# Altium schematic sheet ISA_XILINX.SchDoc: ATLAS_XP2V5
size 558 x 431 mm; Organization: IMP Automatika d.o.o.; Revision: V5
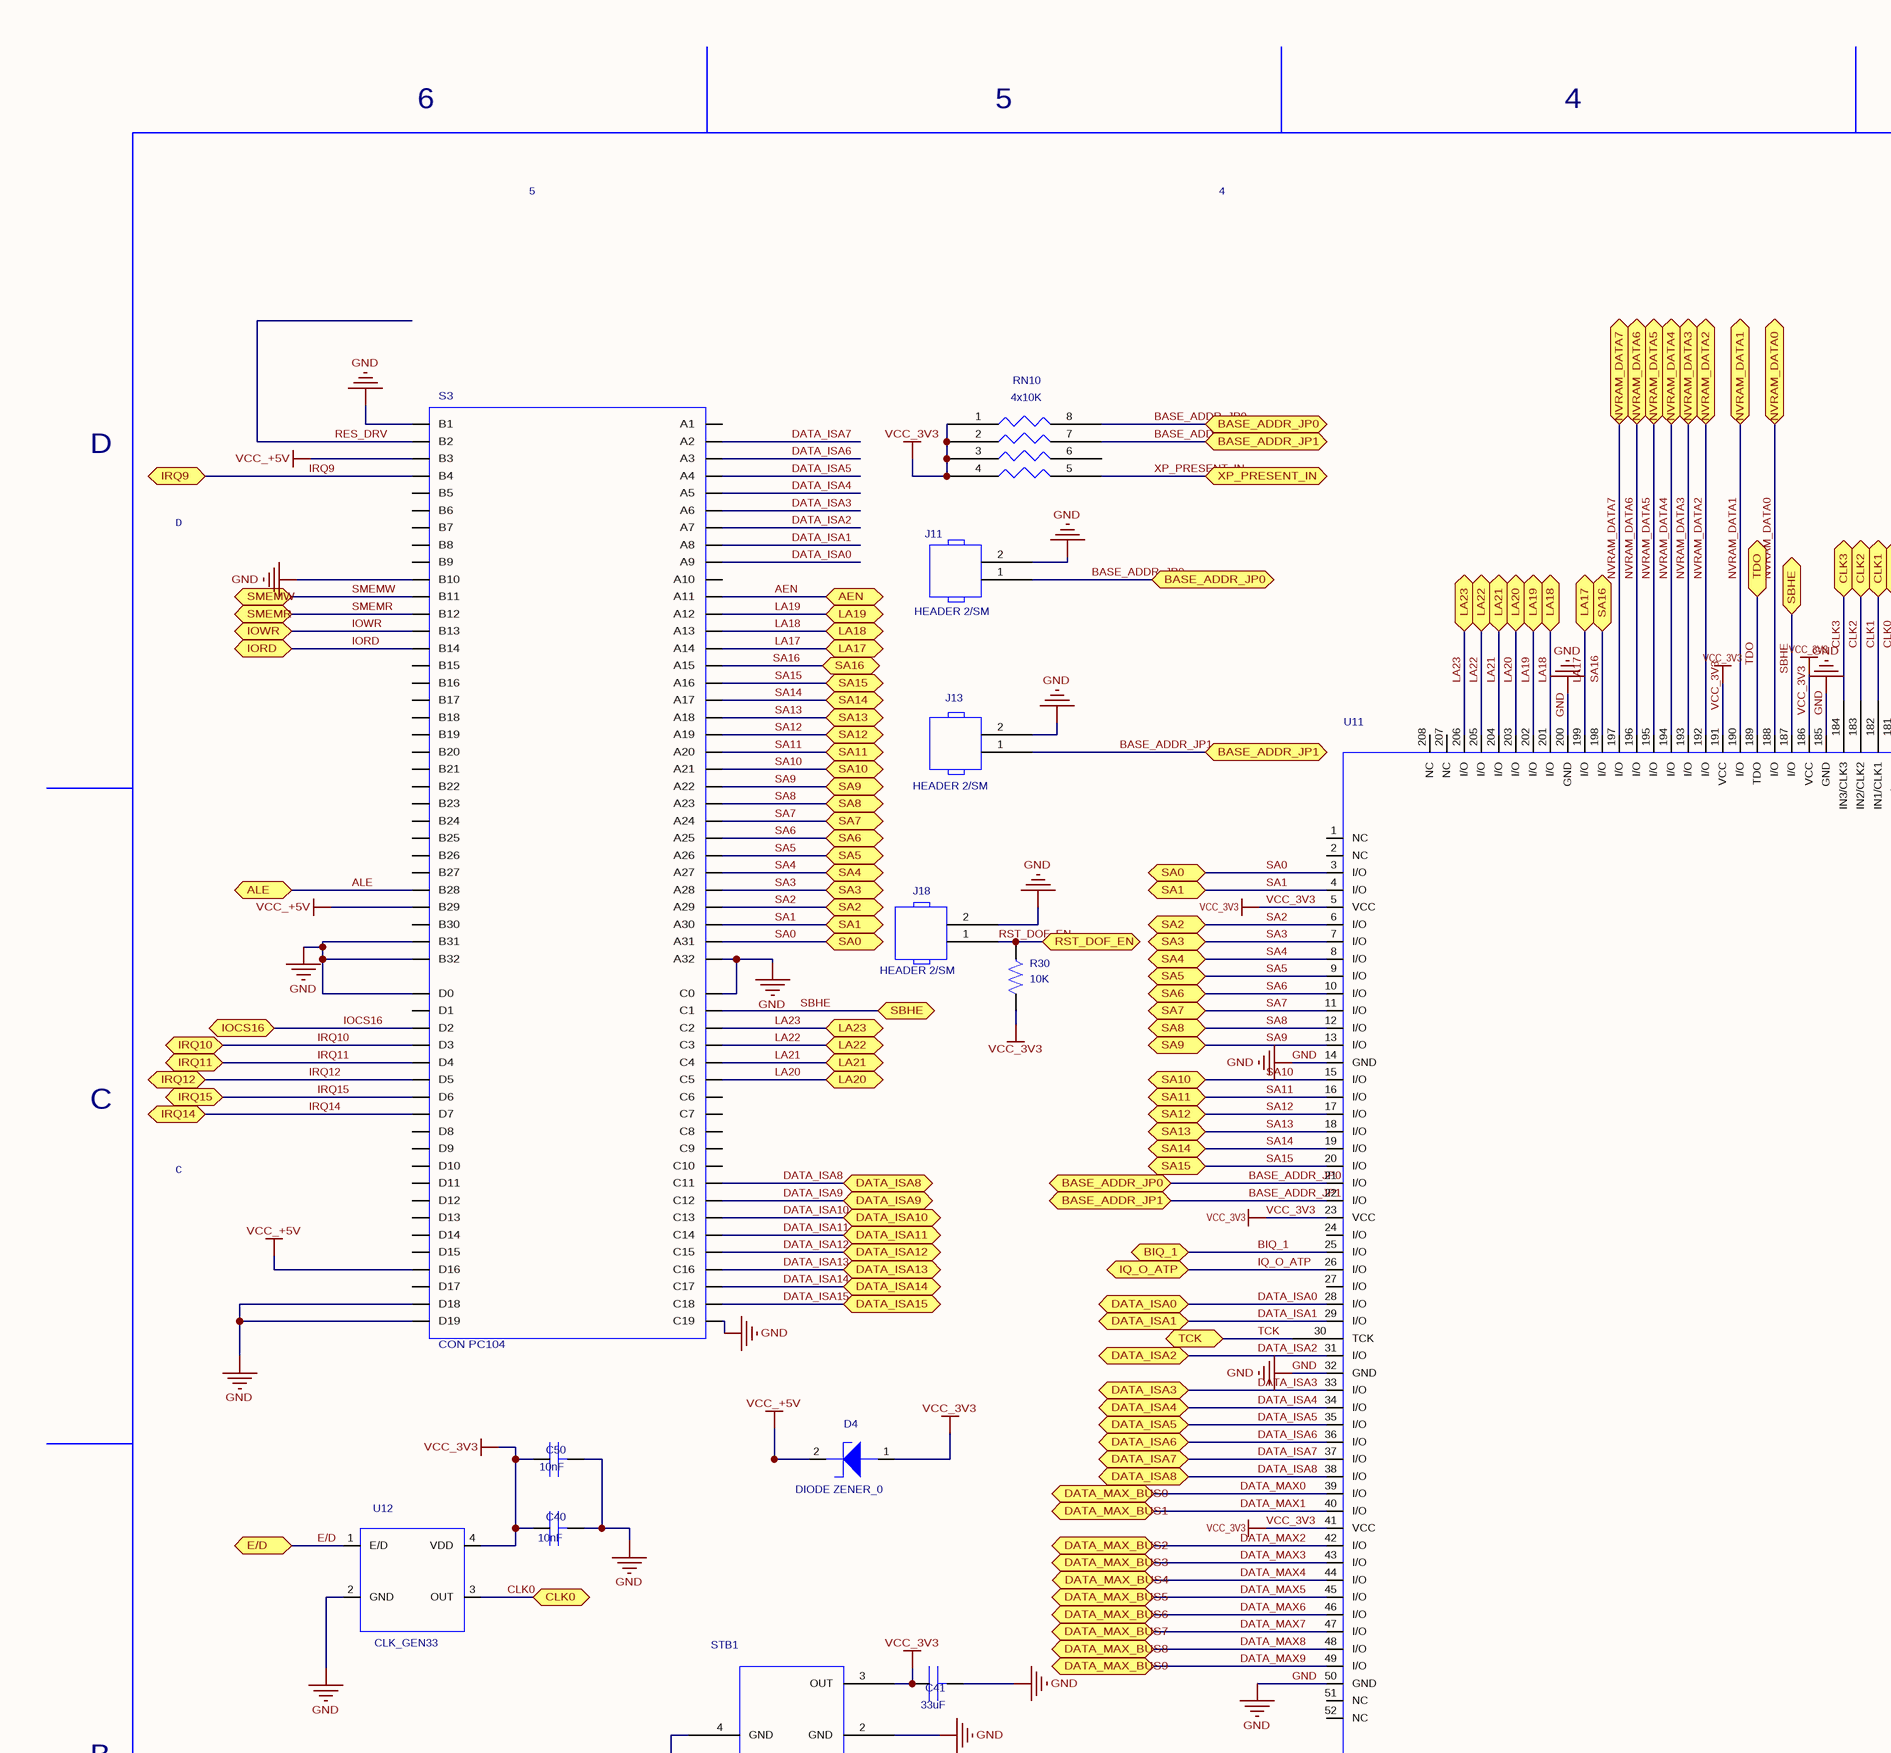
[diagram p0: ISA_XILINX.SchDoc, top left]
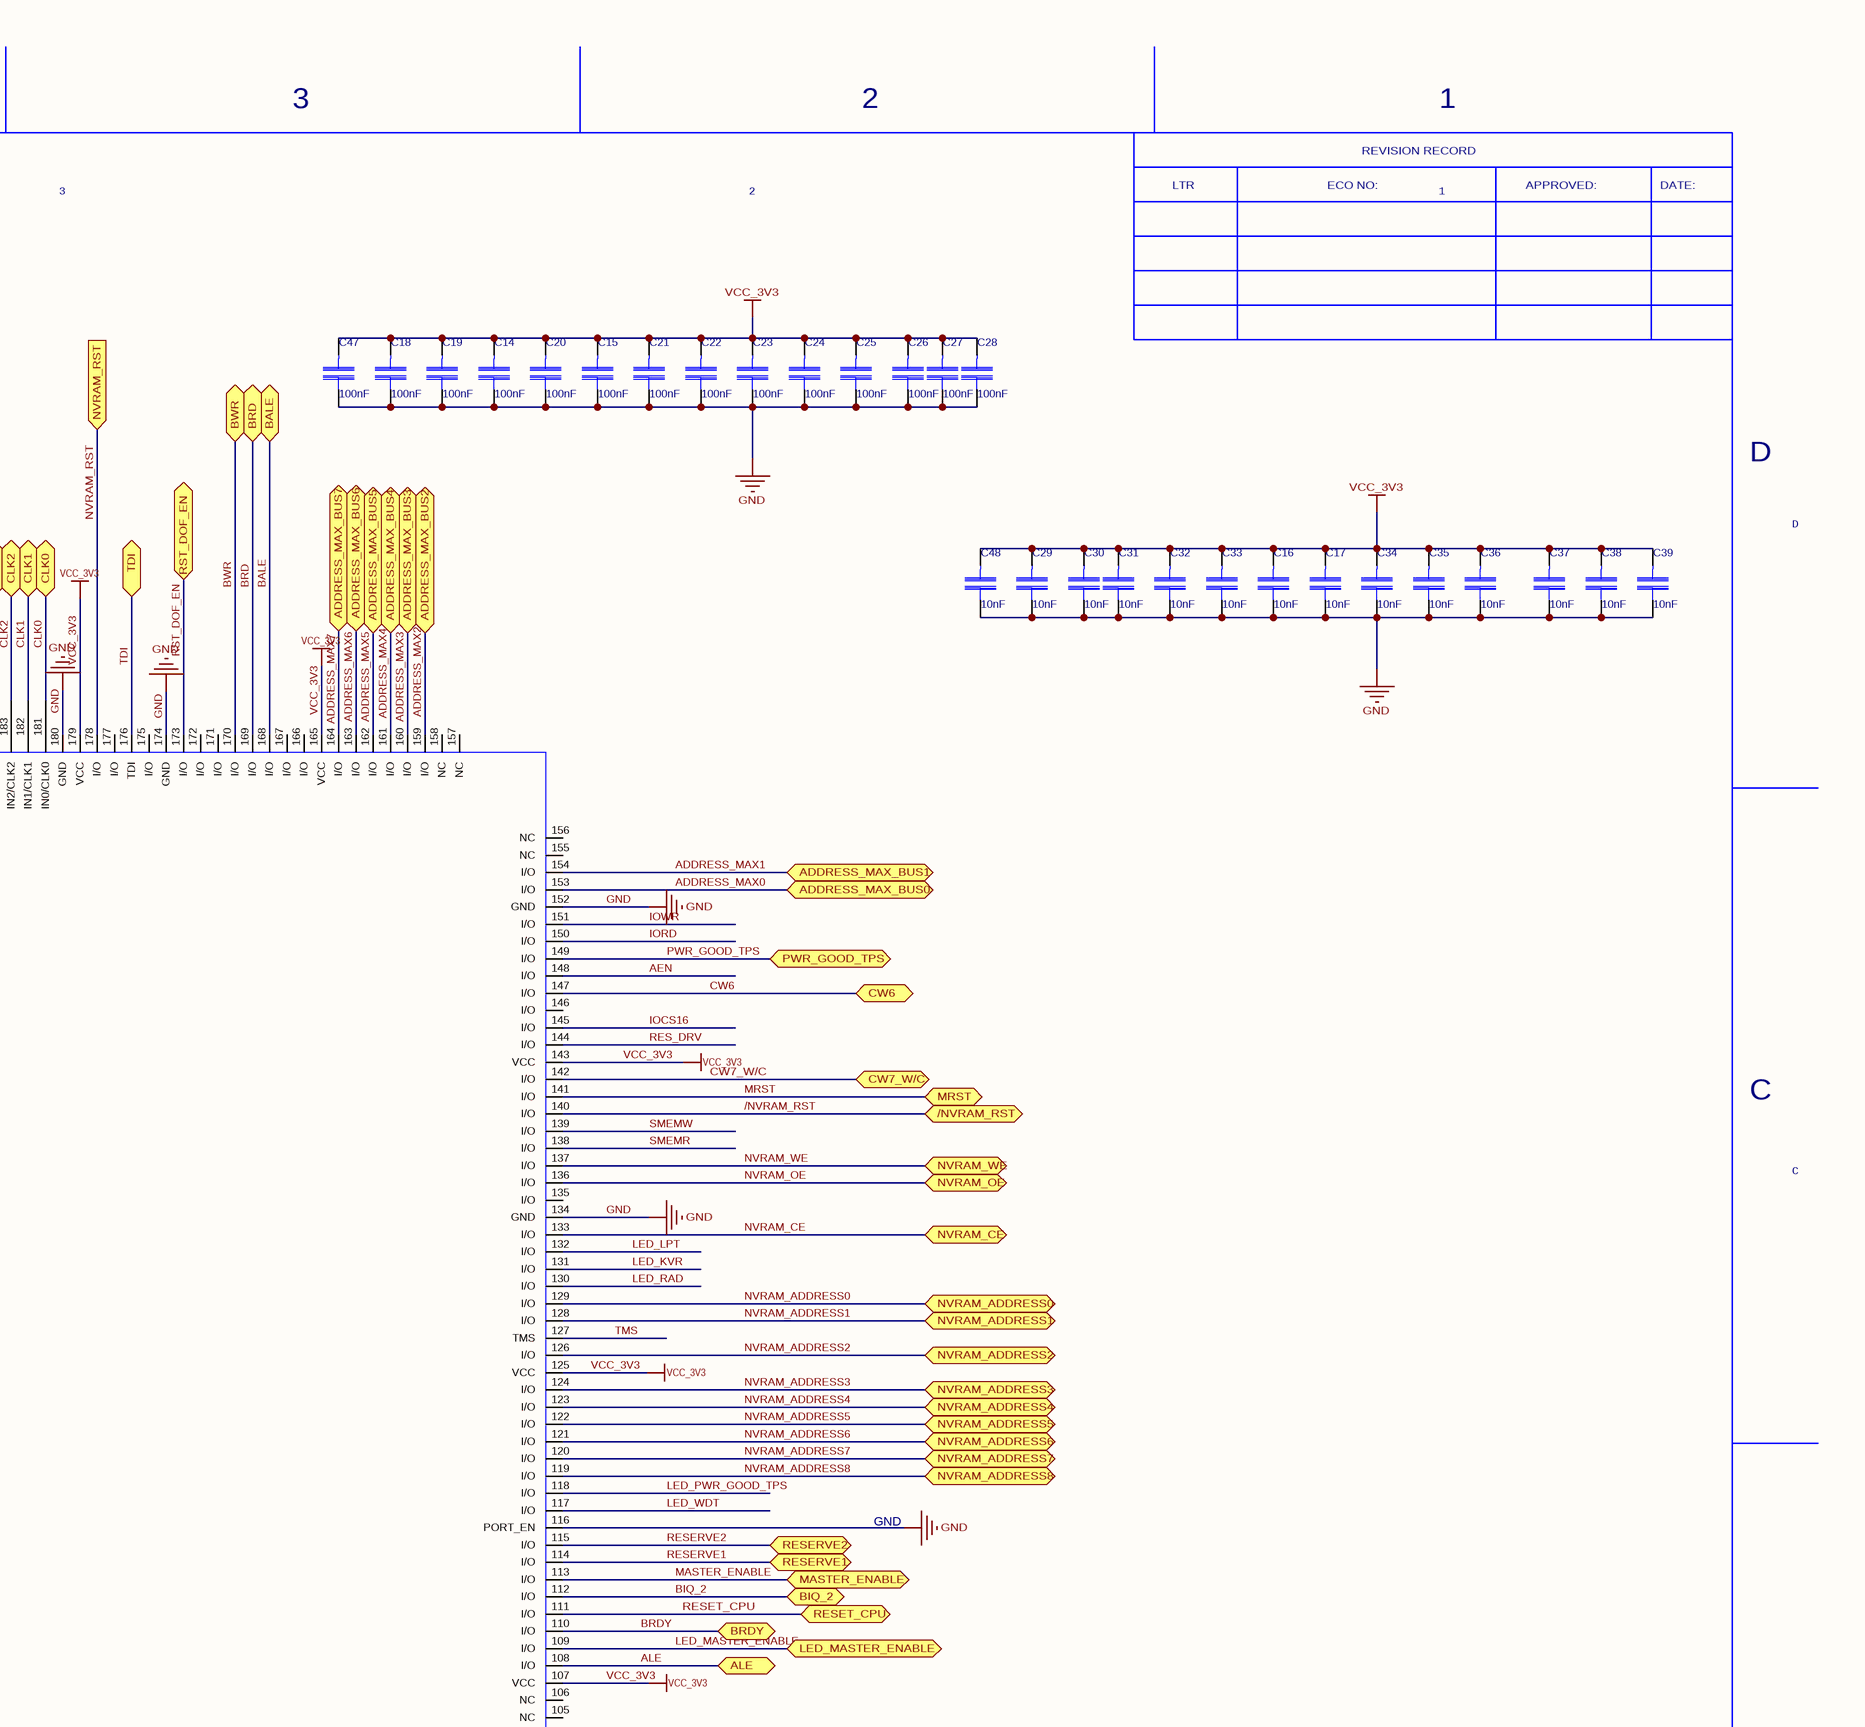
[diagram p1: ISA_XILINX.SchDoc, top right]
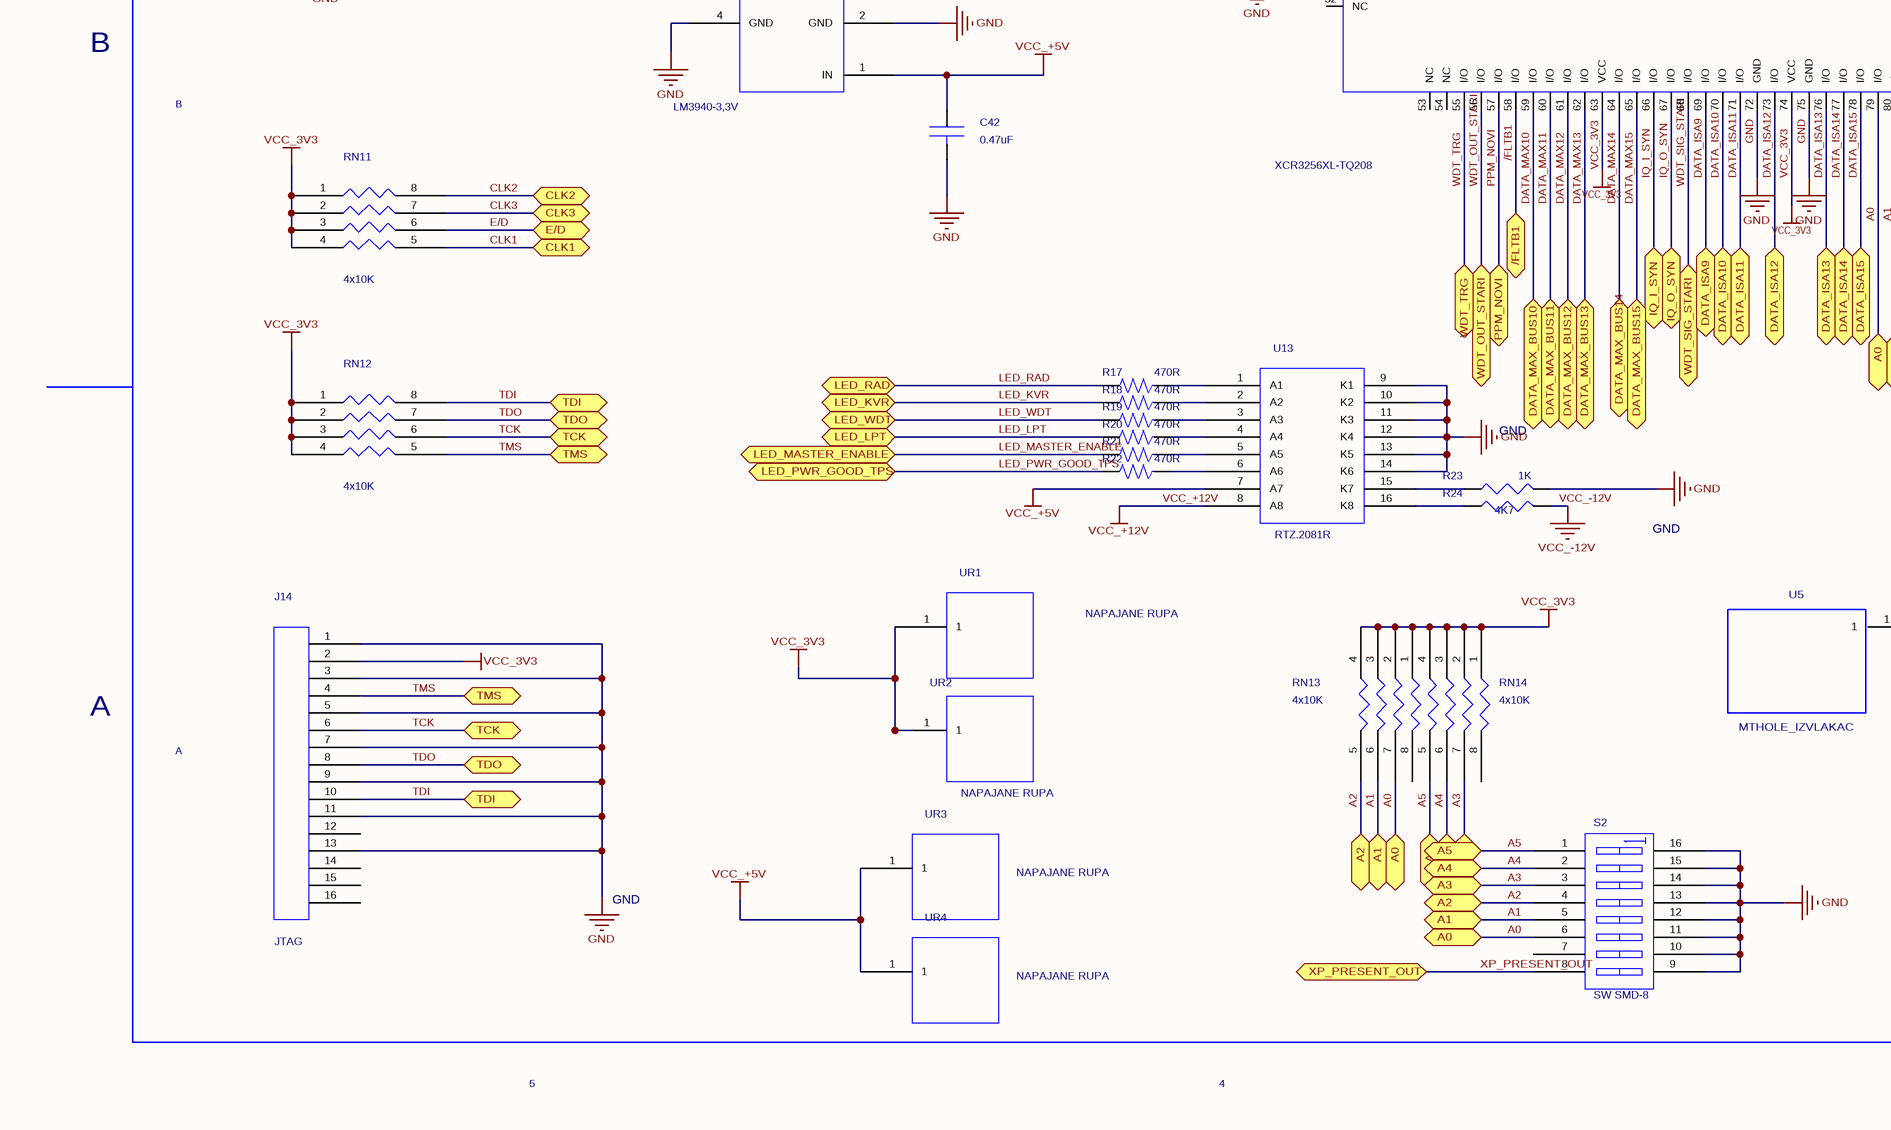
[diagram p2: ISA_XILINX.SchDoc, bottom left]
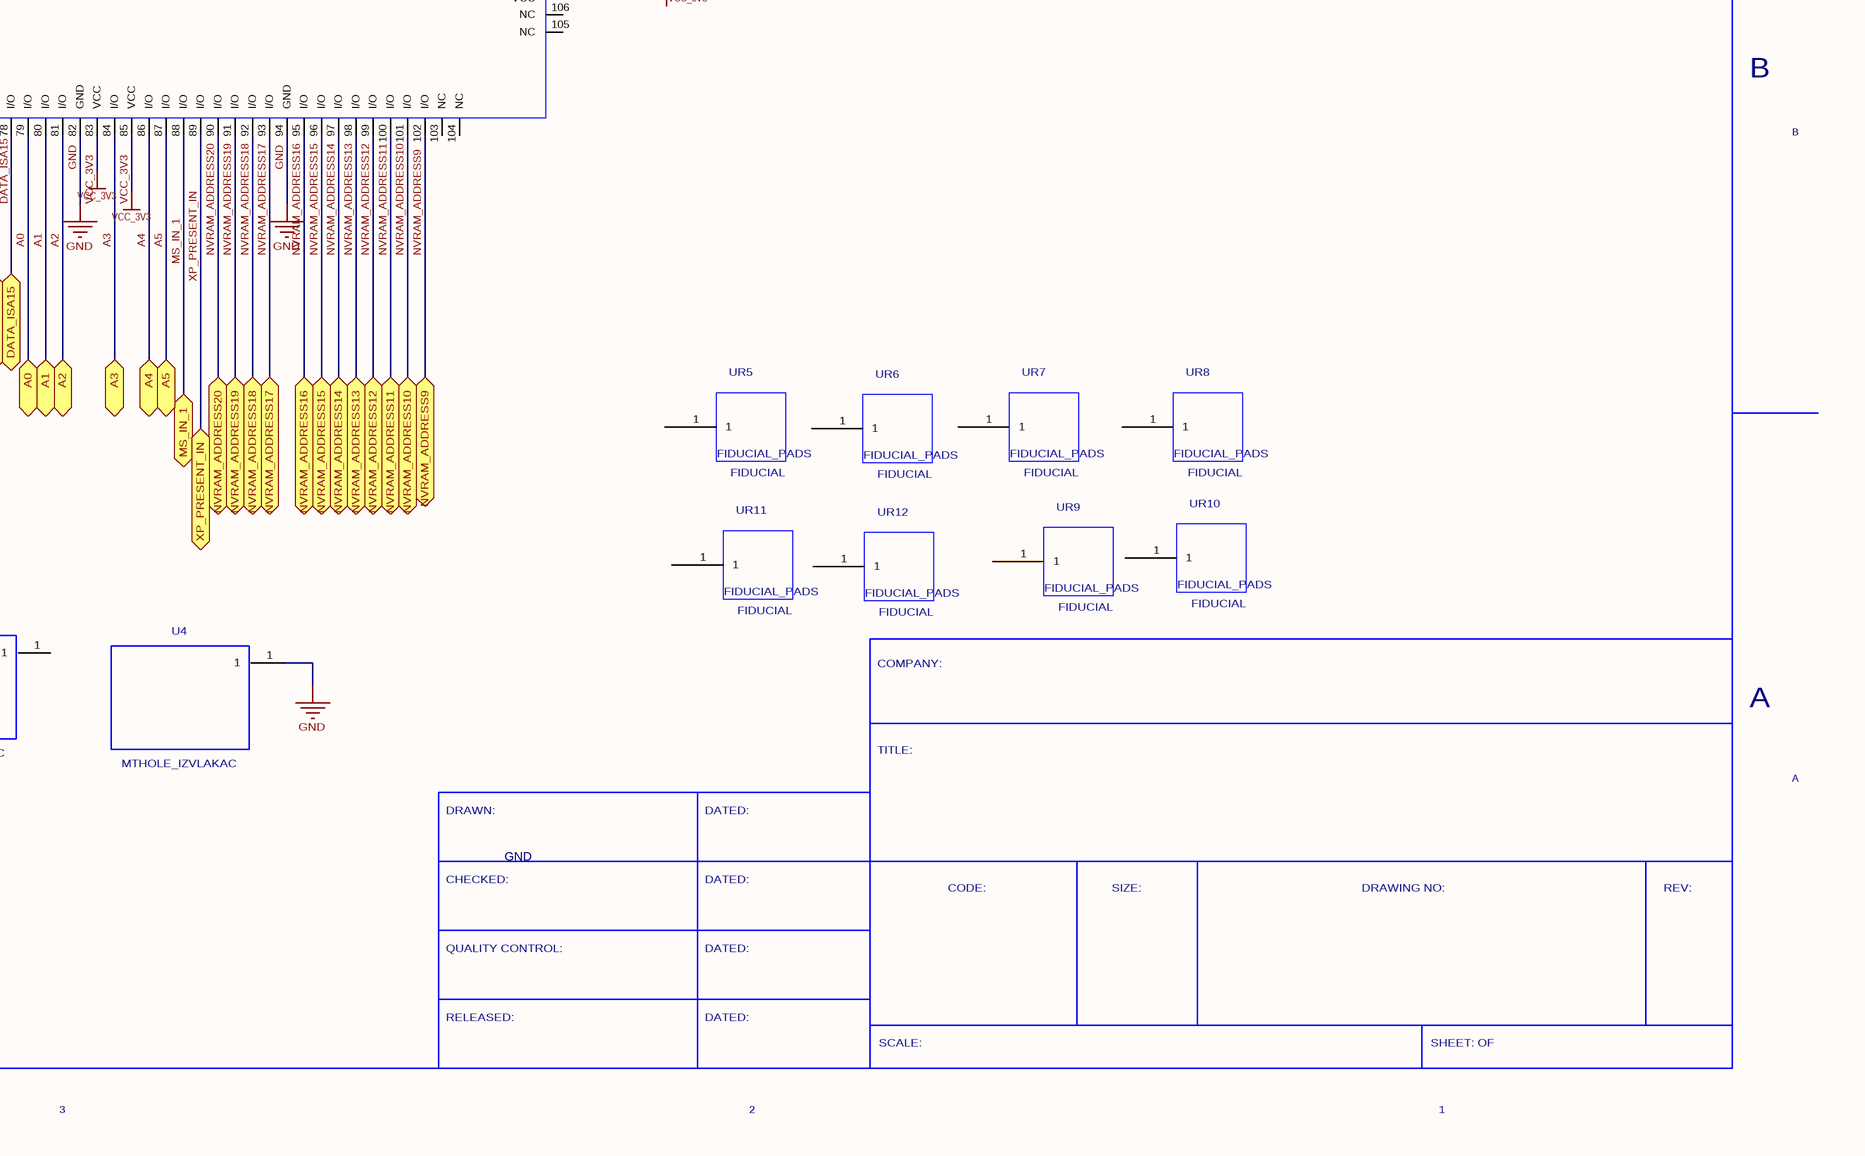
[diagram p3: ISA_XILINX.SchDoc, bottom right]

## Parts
C14  value 100nF  [SM/C_0805]  (hidden comment: C)
C15  value 100nF  [SM/C_0805]  (hidden comment: C)
C16  value 10nF  [SM/C_0805]  (hidden comment: C)
C17  value 10nF  [SM/C_0805]  (hidden comment: C)
C18  value 100nF  [SM/C_0805]  (hidden comment: C)
C19  value 100nF  [SM/C_0805]  (hidden comment: C)
C20  value 100nF  [SM/C_0805]  (hidden comment: C)
C21  value 100nF  [SM/C_0805]  (hidden comment: C)
C22  value 100nF  [SM/C_0805]  (hidden comment: C)
C23  value 100nF  [SM/C_0805]  (hidden comment: C)
C24  value 100nF  [SM/C_0805]  (hidden comment: C)
C25  value 100nF  [SM/C_0805]  (hidden comment: C)
C26  value 100nF  [SM/C_0805]  (hidden comment: C)
C27  value 100nF  [SM/C_0805]  (hidden comment: C)
C28  value 100nF  [SM/C_0805]  (hidden comment: C)
C29  value 10nF  [SM/C_0805]  (hidden comment: C)
C30  value 10nF  [SM/C_0805]  (hidden comment: C)
C31  value 10nF  [SM/C_0805]  (hidden comment: C)
C32  value 10nF  [SM/C_0805]  (hidden comment: C)
C33  value 10nF  [SM/C_0805]  (hidden comment: C)
C34  value 10nF  [SM/C_0805]  (hidden comment: C)
C35  value 10nF  [SM/C_0805]  (hidden comment: C)
C36  value 10nF  [SM/C_0805]  (hidden comment: C)
C37  value 10nF  [SM/C_0805]  (hidden comment: C)
C38  value 10nF  [SM/C_0805]  (hidden comment: C)
C39  value 10nF  [SM/C_0805]  (hidden comment: C)
C40  value 10nF  [SM/C_0805]  (hidden comment: C_4)
C41  value 33uF  [CASE_D_MILOS]  (hidden comment: C_4)
C42  value 0.47uF  [CASE_B_MILOS]  (hidden comment: C_4)
C47  value 100nF  [SM/C_0805]  (hidden comment: C)
C48  value 10nF  [SM/C_0805]  (hidden comment: C)
C50  value 10nF  [SM/C_0805]  (hidden comment: C_4)
D4  value DIODE ZENER_0  [BZV55-C3V3]  (hidden comment: DIODE_ZENER_1)
J11  value HEADER 2/SM  [JUMPER_100]  (hidden comment: HEADER_2/SM)
J13  value HEADER 2/SM  [JUMPER_100]  (hidden comment: HEADER_2/SM)
J14  value JTAG  [JTAG_SMD_REV2]  (hidden comment: CONN_FLEX_16/SM)
J18  value HEADER 2/SM  [JUMPER_100]  (hidden comment: HEADER_2/SM)
R17  value 470R  [SM/R_1206]  (hidden comment: R)
R18  value 470R  [SM/R_1206]  (hidden comment: R)
R19  value 470R  [SM/R_1206]  (hidden comment: R)
R20  value 470R  [SM/R_1206]  (hidden comment: R)
R21  value 470R  [SM/R_1206]  (hidden comment: R)
R22  value 470R  [SM/R_1206]  (hidden comment: R)
R23  value 1K  [SM/R_1206]  (hidden comment: RESISTOR_2)
R24  value 4K7  [SM/R_1206]  (hidden comment: RESISTOR_2)
R30  value 10K  [SM/R_1206]  (hidden comment: R)
RN10  value 4x10K  [SMD_RX4]  (hidden comment: RESAR_IS_4/SM)
RN11  value 4x10K  [SMD_RX4]  (hidden comment: RESAR_IS_4/SM)
RN12  value 4x10K  [SMD_RX4]  (hidden comment: RESAR_IS_4/SM)
RN13  value 4x10K  [SMD_RX4]  (hidden comment: RESAR_IS_4/SM)
RN14  value 4x10K  [SMD_RX4]  (hidden comment: RESAR_IS_4/SM)
S2  value SW SMD-8  [SMD_DIPSW_100]  (hidden comment: SW_DIP-8)
S3  value CON PC104  [PC104_REV13]  (hidden comment: CON_EISAE_0)
STB1  value LM3940-3,3V  [TO263AA_GND_PLANE_REV1]  (hidden comment: LM3940-3_3V)
U4  MTHOLE_IZVLAKAC  [MTH_IZVLAKAC_PADS]
U5  MTHOLE_IZVLAKAC  [MTH_IZVLAKAC_PADS]
U11  XCR3256XL-TQ208  [QUAD.50M/208/WG30.60]
U12  CLK_GEN33  [CLK_GEN33_REV1]
U13  value RTZ.2081R  [LED_8_REV3_PADS]  (hidden comment: LED8X1)
UR1  value NAPAJANE RUPA  [NAPAJANJE_RUPA_REV1]  (hidden comment: NAPAJANE_RUPA)
UR2  value NAPAJANE RUPA  [NAPAJANJE_RUPA_REV1]  (hidden comment: NAPAJANE_RUPA)
UR3  value NAPAJANE RUPA  [NAPAJANJE_RUPA_REV1]  (hidden comment: NAPAJANE_RUPA)
UR4  value NAPAJANE RUPA  [NAPAJANJE_RUPA_REV1]  (hidden comment: NAPAJANE_RUPA)
UR5  FIDUCIAL_PADS  value FIDUCIAL  [FIDUCIAL_R_TOP]
UR6  FIDUCIAL_PADS  value FIDUCIAL  [FIDUCIAL_R_TOP]
UR7  FIDUCIAL_PADS  value FIDUCIAL  [FIDUCIAL_R_TOP]
UR8  FIDUCIAL_PADS  value FIDUCIAL  [FIDUCIAL_R_TOP]
UR9  FIDUCIAL_PADS  value FIDUCIAL  [FIDUCIAL_R_TOP]
UR10  FIDUCIAL_PADS  value FIDUCIAL  [FIDUCIAL_R_TOP]
UR11  FIDUCIAL_PADS  value FIDUCIAL  [FIDUCIAL_R_TOP]
UR12  FIDUCIAL_PADS  value FIDUCIAL  [FIDUCIAL_R_TOP]

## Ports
/FLTB1 (bidir), /NVRAM_RST (bidir), A0 (bidir), A1 (bidir), A2 (bidir), A3 (bidir), A4 (bidir), A5 (bidir), ADDRESS_MAX_BUS0 (bidir), ADDRESS_MAX_BUS1 (bidir), ADDRESS_MAX_BUS2 (bidir), ADDRESS_MAX_BUS3 (bidir), ADDRESS_MAX_BUS4 (bidir), ADDRESS_MAX_BUS5 (bidir), ADDRESS_MAX_BUS6 (bidir), ADDRESS_MAX_BUS7 (bidir), AEN (bidir), ALE (bidir), BALE (bidir), BASE_ADDR_JP0 (bidir), BASE_ADDR_JP1 (bidir), BIQ_1 (bidir), BIQ_2 (bidir), BRD (bidir), BRDY (bidir), BWR (bidir), CLK0 (bidir), CLK1 (bidir), CLK2 (bidir), CLK3 (bidir), CW6 (bidir), CW7_W/C (bidir), DATA_ISA0 (bidir), DATA_ISA1 (bidir), DATA_ISA2 (bidir), DATA_ISA3 (bidir), DATA_ISA4 (bidir), DATA_ISA5 (bidir), DATA_ISA6 (bidir), DATA_ISA7 (bidir), DATA_ISA8 (bidir), DATA_ISA9 (bidir), DATA_ISA10 (bidir), DATA_ISA11 (bidir), DATA_ISA12 (bidir), DATA_ISA13 (bidir), DATA_ISA14 (bidir), DATA_ISA15 (bidir), DATA_MAX_BUS0 (bidir), DATA_MAX_BUS1 (bidir), DATA_MAX_BUS2 (bidir), DATA_MAX_BUS3 (bidir), DATA_MAX_BUS4 (bidir), DATA_MAX_BUS5 (bidir), DATA_MAX_BUS6 (bidir), DATA_MAX_BUS7 (bidir), DATA_MAX_BUS8 (bidir), DATA_MAX_BUS9 (bidir), DATA_MAX_BUS10 (bidir), DATA_MAX_BUS11 (bidir), DATA_MAX_BUS12 (bidir), DATA_MAX_BUS13 (bidir), DATA_MAX_BUS14 (bidir), DATA_MAX_BUS15 (bidir), E/D (bidir), IOCS16 (bidir), IORD (bidir), IOWR (bidir), IQ_I_SYN (bidir), IQ_O_ATP (bidir), IQ_O_SYN (bidir), IRQ9 (bidir), IRQ10 (bidir), IRQ11 (bidir), IRQ12 (bidir), IRQ14 (bidir), IRQ15 (bidir), LA17 (bidir), LA18 (bidir), LA19 (bidir), LA20 (bidir), LA21 (bidir), LA22 (bidir), LA23 (bidir), LED_KVR (bidir), LED_LPT (bidir), LED_MASTER_ENABLE (bidir), LED_PWR_GOOD_TPS (bidir), LED_RAD (bidir), LED_WDT (bidir), MASTER_ENABLE (bidir), MRST (bidir), MS_IN_1 (bidir), NVRAM_ADDRESS0 (bidir), NVRAM_ADDRESS1 (bidir), NVRAM_ADDRESS2 (bidir), NVRAM_ADDRESS3 (bidir), NVRAM_ADDRESS4 (bidir), NVRAM_ADDRESS5 (bidir), NVRAM_ADDRESS6 (bidir), NVRAM_ADDRESS7 (bidir), NVRAM_ADDRESS8 (bidir), NVRAM_ADDRESS9 (bidir), NVRAM_ADDRESS10 (bidir), NVRAM_ADDRESS11 (bidir), NVRAM_ADDRESS12 (bidir), NVRAM_ADDRESS13 (bidir), NVRAM_ADDRESS14 (bidir), NVRAM_ADDRESS15 (bidir), NVRAM_ADDRESS16 (bidir), NVRAM_ADDRESS17 (bidir), NVRAM_ADDRESS18 (bidir), NVRAM_ADDRESS19 (bidir), NVRAM_ADDRESS20 (bidir), NVRAM_CE (bidir), NVRAM_DATA0 (bidir), NVRAM_DATA1 (bidir), NVRAM_DATA2 (bidir), NVRAM_DATA3 (bidir), NVRAM_DATA4 (bidir), NVRAM_DATA5 (bidir), NVRAM_DATA6 (bidir), NVRAM_DATA7 (bidir), NVRAM_OE (bidir), NVRAM_RST, NVRAM_WE (bidir), PPM_NOVI (bidir), PWR_GOOD_TPS (bidir), RESERVE1 (bidir), RESERVE2 (bidir), RESET_CPU (bidir), RST_DOF_EN (bidir), SA0 (bidir), SA1 (bidir), SA2 (bidir), SA3 (bidir), SA4 (bidir), SA5 (bidir), SA6 (bidir), SA7 (bidir), SA8 (bidir), SA9 (bidir), SA10 (bidir), SA11 (bidir), SA12 (bidir), SA13 (bidir), SA14 (bidir), SA15 (bidir), SA16 (bidir), SBHE (bidir), SMEMR (bidir), SMEMW (bidir), TCK (bidir), TDI (bidir), TDO (bidir), TMS (bidir), WDT_OUT_STARI (bidir), WDT_SIG_STARI (bidir), WDT_TRG (bidir), XP_PRESENT_IN (bidir), XP_PRESENT_OUT (bidir)

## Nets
GND: C14.2 C15.2 C16.2 C17.2 C18.2 C19.2 C20.2 C21.2 C22.2 C23.2 C24.2 C25.2 C26.2 C27.2 C28.2 C29.2 C30.2 C31.2 C32.2 C33.2 C34.2 C35.2 C36.2 C37.2 C38.2 C39.2 C40.2 C41.2 C42.2 C47.2 C48.2 C50.2 J11.2 J13.2 J14.1 J14.3 J14.5 J14.7 J14.9 J14.11 J14.13 J18.2 R23.2 S2.9(B8) S2.10(B7) S2.11(B6) S2.12(B5) S2.13(B4) S2.14(B3) S2.15(B2) S2.16(B1) S3.A32 S3.B1 S3.B10 S3.B31 S3.B32 S3.C0 S3.C19 S3.D0 S3.D18 S3.D19 STB1.2(GND) STB1.4(GND) U4.1 U11.14(GND) U11.32(GND) U11.50(GND) U11.72(GND) U11.75(GND) U11.82(GND) U11.94(GND) U11.116(PORT_EN) U11.134(GND) U11.152(GND) U11.174(GND) U11.180(GND) U11.185(GND) U11.200(GND) U12.2(GND) U13.9(K1) U13.10(K2) U13.11(K3) U13.12(K4) U13.13(K5) U13.14(K6)
VCC_3V3: C14.1 C15.1 C16.1 C17.1 C18.1 C19.1 C20.1 C21.1 C22.1 C23.1 C24.1 C25.1 C26.1 C27.1 C28.1 C29.1 C30.1 C31.1 C32.1 C33.1 C34.1 C35.1 C36.1 C37.1 C38.1 C39.1 C40.1 C41.1 C47.1 C48.1 C50.1 D4.1(ANODE) J14.2 R30.2 RN10.1 RN10.2 RN10.3 RN10.4 RN11.1 RN11.2 RN11.3 RN11.4 RN12.1 RN12.2 RN12.3 RN12.4 RN13.1 RN13.2 RN13.3 RN13.4 RN14.1 RN14.2 RN14.3 RN14.4 STB1.3(OUT) U11.5(VCC) U11.23(VCC) U11.41(VCC) U11.63(VCC) U11.74(VCC) U11.83(VCC) U11.85(VCC) U11.107(VCC) U11.125(VCC) U11.143(VCC) U11.165(VCC) U11.179(VCC) U11.186(VCC) U11.191(VCC) U12.4(VDD) UR1.1 UR2.1
VCC_+5V: C42.1 D4.2(CATHODE) S3.B3 S3.B29 S3.D16 STB1.1(IN) U13.7(A7) UR3.1 UR4.1
VCC_+12V: U13.8(A8)
VCC_-12V: R24.2
/FLTB1: U11.58(I/O) ; port /FLTB1
/NVRAM_RST: U11.140(I/O) ; port /NVRAM_RST
A0: RN13.7 S2.6(A6) U11.79(I/O) ; port A0
A1: RN13.6 S2.5(A5) U11.80(I/O) ; port A1
A2: RN13.5 S2.4(A4) U11.81(I/O) ; port A2
A3: RN14.7 S2.3(A3) U11.84(I/O) ; port A3
A4: RN14.6 S2.2(A2) U11.86(I/O) ; port A4
A5: RN14.5 S2.1(A1) U11.87(I/O) ; port A5
ADDRESS_MAX0: U11.153(I/O) ; port ADDRESS_MAX_BUS0
ADDRESS_MAX1: U11.154(I/O) ; port ADDRESS_MAX_BUS1
ADDRESS_MAX2: U11.159(I/O) ; port ADDRESS_MAX_BUS2
ADDRESS_MAX3: U11.160(I/O) ; port ADDRESS_MAX_BUS3
ADDRESS_MAX4: U11.161(I/O) ; port ADDRESS_MAX_BUS4
ADDRESS_MAX5: U11.162(I/O) ; port ADDRESS_MAX_BUS5
ADDRESS_MAX6: U11.163(I/O) ; port ADDRESS_MAX_BUS6
ADDRESS_MAX7: U11.164(I/O) ; port ADDRESS_MAX_BUS7
AEN: S3.A11 U11.148(I/O) ; port AEN
ALE: S3.B28 U11.108(I/O) ; port ALE
BALE: U11.168(I/O) ; port BALE
BASE_ADDR_JP0: J11.1 RN10.8 U11.21(I/O) ; port BASE_ADDR_JP0
BASE_ADDR_JP1: J13.1 RN10.7 U11.22(I/O) ; port BASE_ADDR_JP1
BIQ_1: U11.25(I/O) ; port BIQ_1
BIQ_2: U11.112(I/O) ; port BIQ_2
BRD: U11.169(I/O) ; port BRD
BRDY: U11.110(I/O) ; port BRDY
BWR: U11.170(I/O) ; port BWR
CLK0: U11.181(IN0/CLK0) U12.3(OUT) ; port CLK0
CLK1: RN11.5 U11.182(IN1/CLK1) ; port CLK1
CLK2: RN11.8 U11.183(IN2/CLK2) ; port CLK2
CLK3: RN11.7 U11.184(IN3/CLK3) ; port CLK3
CW6: U11.147(I/O) ; port CW6
CW7_W/C: U11.142(I/O) ; port CW7_W/C
DATA_ISA0: S3.A9 U11.28(I/O) ; port DATA_ISA0
DATA_ISA1: S3.A8 U11.29(I/O) ; port DATA_ISA1
DATA_ISA2: S3.A7 U11.31(I/O) ; port DATA_ISA2
DATA_ISA3: S3.A6 U11.33(I/O) ; port DATA_ISA3
DATA_ISA4: S3.A5 U11.34(I/O) ; port DATA_ISA4
DATA_ISA5: S3.A4 U11.35(I/O) ; port DATA_ISA5
DATA_ISA6: S3.A3 U11.36(I/O) ; port DATA_ISA6
DATA_ISA7: S3.A2 U11.37(I/O) ; port DATA_ISA7
DATA_ISA8: S3.C11 U11.38(I/O) ; port DATA_ISA8
DATA_ISA9: S3.C12 U11.69(I/O) ; port DATA_ISA9
DATA_ISA10: S3.C13 U11.70(I/O) ; port DATA_ISA10
DATA_ISA11: S3.C14 U11.71(I/O) ; port DATA_ISA11
DATA_ISA12: S3.C15 U11.73(I/O) ; port DATA_ISA12
DATA_ISA13: S3.C16 U11.76(I/O) ; port DATA_ISA13
DATA_ISA14: S3.C17 U11.77(I/O) ; port DATA_ISA14
DATA_ISA15: S3.C18 U11.78(I/O) ; port DATA_ISA15
DATA_MAX0: U11.39(I/O) ; port DATA_MAX_BUS0
DATA_MAX1: U11.40(I/O) ; port DATA_MAX_BUS1
DATA_MAX2: U11.42(I/O) ; port DATA_MAX_BUS2
DATA_MAX3: U11.43(I/O) ; port DATA_MAX_BUS3
DATA_MAX4: U11.44(I/O) ; port DATA_MAX_BUS4
DATA_MAX5: U11.45(I/O) ; port DATA_MAX_BUS5
DATA_MAX6: U11.46(I/O) ; port DATA_MAX_BUS6
DATA_MAX7: U11.47(I/O) ; port DATA_MAX_BUS7
DATA_MAX8: U11.48(I/O) ; port DATA_MAX_BUS8
DATA_MAX9: U11.49(I/O) ; port DATA_MAX_BUS9
DATA_MAX10: U11.59(I/O) ; port DATA_MAX_BUS10
DATA_MAX11: U11.60(I/O) ; port DATA_MAX_BUS11
DATA_MAX12: U11.61(I/O) ; port DATA_MAX_BUS12
DATA_MAX13: U11.62(I/O) ; port DATA_MAX_BUS13
DATA_MAX14: U11.64(I/O) ; port DATA_MAX_BUS14
DATA_MAX15: U11.65(I/O) ; port DATA_MAX_BUS15
E/D: RN11.6 U12.1(E/D) ; port E/D
IOCS16: S3.D2 U11.145(I/O) ; port IOCS16
IORD: S3.B14 U11.150(I/O) ; port IORD
IOWR: S3.B13 U11.151(I/O) ; port IOWR
IQ_I_SYN: U11.66(I/O) ; port IQ_I_SYN
IQ_O_ATP: U11.26(I/O) ; port IQ_O_ATP
IQ_O_SYN: U11.67(I/O) ; port IQ_O_SYN
IRQ9: S3.B4 ; port IRQ9
IRQ10: S3.D3 ; port IRQ10
IRQ11: S3.D4 ; port IRQ11
IRQ12: S3.D5 ; port IRQ12
IRQ14: S3.D7 ; port IRQ14
IRQ15: S3.D6 ; port IRQ15
LA17: S3.A14 U11.199(I/O) ; port LA17
LA18: S3.A13 U11.201(I/O) ; port LA18
LA19: S3.A12 U11.202(I/O) ; port LA19
LA20: S3.C5 U11.203(I/O) ; port LA20
LA21: S3.C4 U11.204(I/O) ; port LA21
LA22: S3.C3 U11.205(I/O) ; port LA22
LA23: S3.C2 U11.206(I/O) ; port LA23
LED_KVR: R18.2 U11.131(I/O) ; port LED_KVR
LED_LPT: R20.2 U11.132(I/O) ; port LED_LPT
LED_MASTER_ENABLE: R21.2 U11.109(I/O) ; port LED_MASTER_ENABLE
LED_PWR_GOOD_TPS: R22.2 U11.118(I/O) ; port LED_PWR_GOOD_TPS
LED_RAD: R17.2 U11.130(I/O) ; port LED_RAD
LED_WDT: R19.2 U11.117(I/O) ; port LED_WDT
MASTER_ENABLE: U11.113(I/O) ; port MASTER_ENABLE
MRST: U11.141(I/O) ; port MRST
MS_IN_1: U11.88(I/O) ; port MS_IN_1
NVRAM_ADDRESS0: U11.129(I/O) ; port NVRAM_ADDRESS0
NVRAM_ADDRESS1: U11.128(I/O) ; port NVRAM_ADDRESS1
NVRAM_ADDRESS2: U11.126(I/O) ; port NVRAM_ADDRESS2
NVRAM_ADDRESS3: U11.124(I/O) ; port NVRAM_ADDRESS3
NVRAM_ADDRESS4: U11.123(I/O) ; port NVRAM_ADDRESS4
NVRAM_ADDRESS5: U11.122(I/O) ; port NVRAM_ADDRESS5
NVRAM_ADDRESS6: U11.121(I/O) ; port NVRAM_ADDRESS6
NVRAM_ADDRESS7: U11.120(I/O) ; port NVRAM_ADDRESS7
NVRAM_ADDRESS8: U11.119(I/O) ; port NVRAM_ADDRESS8
NVRAM_ADDRESS9: U11.102(I/O) ; port NVRAM_ADDRESS9
NVRAM_ADDRESS10: U11.101(I/O) ; port NVRAM_ADDRESS10
NVRAM_ADDRESS11: U11.100(I/O) ; port NVRAM_ADDRESS11
NVRAM_ADDRESS12: U11.99(I/O) ; port NVRAM_ADDRESS12
NVRAM_ADDRESS13: U11.98(I/O) ; port NVRAM_ADDRESS13
NVRAM_ADDRESS14: U11.97(I/O) ; port NVRAM_ADDRESS14
NVRAM_ADDRESS15: U11.96(I/O) ; port NVRAM_ADDRESS15
NVRAM_ADDRESS16: U11.95(I/O) ; port NVRAM_ADDRESS16
NVRAM_ADDRESS17: U11.93(I/O) ; port NVRAM_ADDRESS17
NVRAM_ADDRESS18: U11.92(I/O) ; port NVRAM_ADDRESS18
NVRAM_ADDRESS19: U11.91(I/O) ; port NVRAM_ADDRESS19
NVRAM_ADDRESS20: U11.90(I/O) ; port NVRAM_ADDRESS20
NVRAM_CE: U11.133(I/O) ; port NVRAM_CE
NVRAM_DATA0: U11.188(I/O) ; port NVRAM_DATA0
NVRAM_DATA1: U11.190(I/O) ; port NVRAM_DATA1
NVRAM_DATA2: U11.192(I/O) ; port NVRAM_DATA2
NVRAM_DATA3: U11.193(I/O) ; port NVRAM_DATA3
NVRAM_DATA4: U11.194(I/O) ; port NVRAM_DATA4
NVRAM_DATA5: U11.195(I/O) ; port NVRAM_DATA5
NVRAM_DATA6: U11.196(I/O) ; port NVRAM_DATA6
NVRAM_DATA7: U11.197(I/O) ; port NVRAM_DATA7
NVRAM_OE: U11.136(I/O) ; port NVRAM_OE
NVRAM_RST: U11.178(I/O) ; port NVRAM_RST
NVRAM_WE: U11.137(I/O) ; port NVRAM_WE
PPM_NOVI: U11.57(I/O) ; port PPM_NOVI
PWR_GOOD_TPS: U11.149(I/O) ; port PWR_GOOD_TPS
RES_DRV: S3.B2 U11.144(I/O)
RESERVE1: U11.114(I/O) ; port RESERVE1
RESERVE2: U11.115(I/O) ; port RESERVE2
RESET_CPU: U11.111(I/O) ; port RESET_CPU
RST_DOF_EN: J18.1 R30.1 U11.173(I/O) ; port RST_DOF_EN
SA0: S3.A31 U11.3(I/O) ; port SA0
SA1: S3.A30 U11.4(I/O) ; port SA1
SA2: S3.A29 U11.6(I/O) ; port SA2
SA3: S3.A28 U11.7(I/O) ; port SA3
SA4: S3.A27 U11.8(I/O) ; port SA4
SA5: S3.A26 U11.9(I/O) ; port SA5
SA6: S3.A25 U11.10(I/O) ; port SA6
SA7: S3.A24 U11.11(I/O) ; port SA7
SA8: S3.A23 U11.12(I/O) ; port SA8
SA9: S3.A22 U11.13(I/O) ; port SA9
SA10: S3.A21 U11.15(I/O) ; port SA10
SA11: S3.A20 U11.16(I/O) ; port SA11
SA12: S3.A19 U11.17(I/O) ; port SA12
SA13: S3.A18 U11.18(I/O) ; port SA13
SA14: S3.A17 U11.19(I/O) ; port SA14
SA15: S3.A16 U11.20(I/O) ; port SA15
SA16: S3.A15 U11.198(I/O) ; port SA16
SBHE: S3.C1 U11.187(I/O) ; port SBHE
SMEMR: S3.B12 U11.138(I/O) ; port SMEMR
SMEMW: S3.B11 U11.139(I/O) ; port SMEMW
TCK: J14.6 RN12.6 U11.30(TCK) ; port TCK
TDI: J14.10 RN12.8 U11.176(TDI) ; port TDI
TDO: J14.8 RN12.7 U11.189(TDO) ; port TDO
TMS: J14.4 RN12.5 U11.127(TMS) ; port TMS
WDT_OUT_STARI: U11.56(I/O) ; port WDT_OUT_STARI
WDT_SIG_STARI: U11.68(I/O) ; port WDT_SIG_STARI
WDT_TRG: U11.55(I/O) ; port WDT_TRG
XP_PRESENT_IN: RN10.5 U11.89(I/O) ; port XP_PRESENT_IN
XP_PRESENT_OUT: S2.8(A8) ; port XP_PRESENT_OUT
NetR17_1: R17.1 U13.1(A1)
NetR18_1: R18.1 U13.2(A2)
NetR19_1: R19.1 U13.3(A3)
NetR20_1: R20.1 U13.4(A4)
NetR21_1: R21.1 U13.5(A5)
NetR22_1: R22.1 U13.6(A6)
NetR23_1: R23.1 U13.15(K7)
NetR24_1: R24.1 U13.16(K8)

Not connected (* = marked no-connect by the designer): J14 12 14 15 16; RN10 6; RN13 8; RN14 8; S2 7(A7); S3 A1 A10 B5 B6 B7 B8 B9 B15 B16 B17 B18 B19 B20 B21 B22 B23 B24 B25 B26 B27 B30 C6 C7 C8 C9 C10 D1 D8 D9 D10 D11 D12 D13 D14 D15 D17; U5 1; U11 1(NC) 2(NC) 24(I/O) 27(I/O) 51(NC) 52(NC) 53(NC) 54(NC) 103(NC) 104(NC) 105(NC) 106(NC) 135(I/O) 146(I/O) 155(NC) 156(NC) 157(NC) 158(NC) 166(I/O) 167(I/O) 171(I/O) 172(I/O) 175(I/O) 177(I/O) 207(NC) 208(NC); UR5 1; UR6 1; UR7 1; UR8 1; UR9 1; UR10 1; UR11 1; UR12 1

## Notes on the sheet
- 6
- 5
- 4
- 3
- 2
- 1
- LTR
- ECO NO:
- REVISION RECORD
- APPROVED:
- DATE:
- D
- C
- GND
- B
- COMPANY:
- A
- TITLE:
- DRAWN:
- DATED:
- CHECKED:
- CODE:
- SIZE:
- DRAWING NO:
- REV:
- QUALITY CONTROL:
- RELEASED:
- SCALE:
- SHEET: OF
- Labels drawn without touching a wire or pin: VCC_3V3

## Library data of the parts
C14-C39 C47 C48 = C: Source_Path: D:\ORCADWIN\CAPTURE\ATP_LATT_01\ATP_00.OLB; SDTSourceLibName: C:\WINDOWS\TEMP\ATP_00.LIB
C40-C42 C50 = C_4: Source_Path: C:\ORCAD\ORCAD_10.5\TOOLS\CAPTURE\LIBRARY\IEC\DEVICE.OLB
D4 = DIODE_ZENER_1: Source_Path: E:\MILOS\PROJECTS\ATLAS_XP2V3\ATLAS_XP2V3.DSN
J11 J13 J18 = HEADER_2/SM: Source_Path: C:\ORCAD\ORCAD_10.5\TOOLS\CAPTURE\LIBRARY\CONNECTOR.OLB
J14 = CONN_FLEX_16/SM: Source_Path: C:\ORCAD\ORCAD_10.5\TOOLS\CAPTURE\LIBRARY\CONNECTOR.OLB
R17-R22 R30 = R: Source_Path: C:\ORCAD\ORCAD_10.0\TOOLS\CAPTURE\LIBRARY\PSPICE\ANALOG.OLB; DIST: FLAT; PSpiceTemplate: R^@REFDES %1 %2 ?TOLERANCE¦R^@REFDES¦ @VALUE  ?TOLERANCE¦\n.model R^@REFDES RES R=1 DEV=@TOLERANCE%¦; VOLTAGE: RVMAX; SLOPE: RSMAX; MAX_TEMP: RTMAX; POWER: RMAX
R23 R24 = RESISTOR_2: Source_Path: C:\CADENCE\PSD_15.1\TOOLS\CAPTURE\LIBRARY\DISCRETE.OLB
RN10-RN14 = RESAR_IS_4/SM: Source_Path: C:\ORCAD\ORCAD_10.5\TOOLS\CAPTURE\LIBRARY\DISCRETE.OLB
S2 = SW_DIP-8: Source_Path: C:\CADENCE\PSD_15.1\TOOLS\CAPTURE\LIBRARY\OLDLIBS\DEVICE.OLB
S3 = CON_EISAE_0: Source_Path: C:\CADENCE\PSD_15.1\TOOLS\ATLAS_ITA\ATLAS_ITA.DSN
STB1 = LM3940-3_3V: Source_Path: C:\PROJECTS\VHDL_PROJEKTI\DIS32\BIS32_16\BIS32_16.OLB
U4 U5 = MTHOLE_IZVLAKAC: Rupa za Rittal-ov izvlakac
U11 = XCR3256XL-TQ208: Source_Path: C:\PROJECTS\XILINX_ORCAD_LIB\XILINX.OLB
U12 = CLK_GEN33: Source_Path: C:\PROJECTS\VHDL_PROJEKTI\DIS32\BIS32_16\BIS32_16.OLB
U13 = LED8X1: Source_Path: C:\CADENCE\PSD_15.1\TOOLS\ATLAS_ITA\LIBRARY1.OLB; Geometry.Height: 5.08mm; Order No: 31 G 7692 Buerklin
UR1-UR4 = NAPAJANE_RUPA: Source_Path: E:\MILOS\PROJECTS\OBRTOMER\BPC02REV1\LIBRARY1.OLB
UR5-UR12 = FIDUCIAL_PADS: Source_Path: C:\BEKAP STAROG RACUNARA\FOHUB1\FO-HUB1VER.1.01\FOHUB1\SEME\HFBR0050Z.OLB; Geometry.Height: 10.00mil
